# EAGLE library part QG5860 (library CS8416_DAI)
CRYSTAL RESONATOR
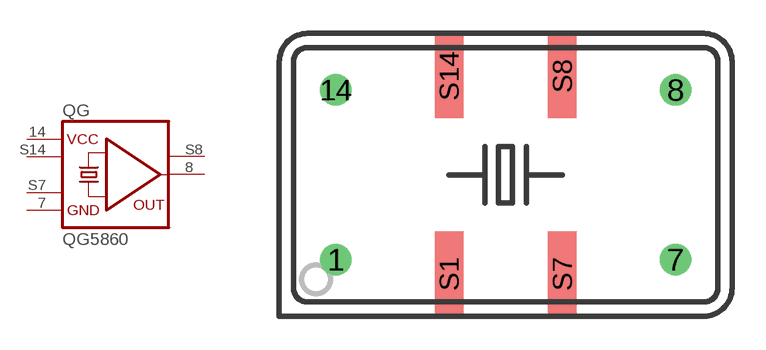
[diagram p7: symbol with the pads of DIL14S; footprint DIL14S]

Designator prefix QG

## QG5860  [DIL14S]
7  GND  pwr
8  OUT  out
14  VCC  pwr
S7  GND  pwr
S8  OUT
S14  VCC  pwr

## Footprint DIL14S (pad centres in mm)
CRYSTAL RESONATOR
drill 0.889 pad 1.422 round: 1 -7.62,-3.81; 7 7.62,-3.81; 8 7.62,3.81; 14 -7.62,3.81
smd 1.27 x 3.81: S1 -2.54,-4.445; S7 2.54,-4.445; S8 2.54,4.445; S14 -2.54,4.445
